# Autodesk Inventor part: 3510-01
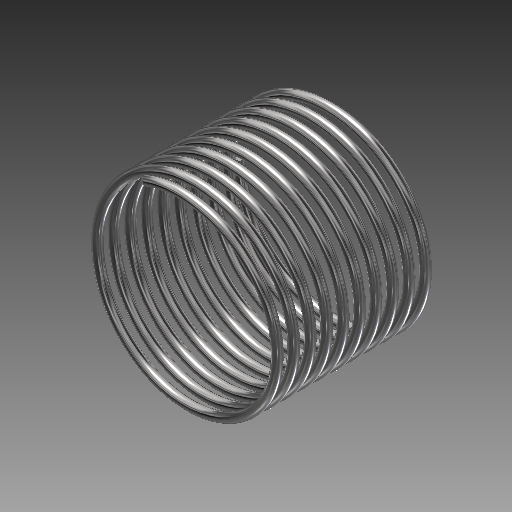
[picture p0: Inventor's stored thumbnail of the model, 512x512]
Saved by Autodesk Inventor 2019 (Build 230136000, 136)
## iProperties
Company: Autodesk Inc.
Created: 2008-12
Part Number: 3510-01
Document SubType Name: Modeling
Designer: Autodesk Inc.
Density: 7.85 g/cm^3
Mass: 0.243154 g
Surface Area: 3.0999 cm^2
Volume: 0.030975 cm^3
Material: Steel
Appearance: Semi-Polished
Description: RETAINER SPRING
Author: Inventor
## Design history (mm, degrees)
sketch "Sketch1"
  geometry: A1 r 4.5 centre (0, 0) between (4, 2.062) and (4, -2.062)
  constraints: 2 point on circle, 1 centre point
workaxis "Work Axis1"
  workplane "Work Plane1"
workplane "Work Plane2"
sketch "Sketch2"
  geometry: L1 (-15.142, -1.445)-(-5.367, -1.445) reference; C1 r 0.2 at (-15.967, -8.192); 1 further point
  constraints: 1 centre point
  dimensions: "d0" = 4 horizontal distance of point (-19.967, -8.392) C1.centre; "d1" = 0.2 vertical distance of C1.centre point (-19.967, -8.392); "d2" = 0.4 diameter of C1
coil "Coil1" sketch "Sketch2" pitch "d3" = 0.7; turns "d5" = 1; dims "d4" = 6.6, "d6" = 0, angle "d7" = 90 deg, angle "d8" = 90 deg, "d9" = 0, "d10" = 0
workpoint "Work Point1"
body "Solid1"
node "Reference2"
